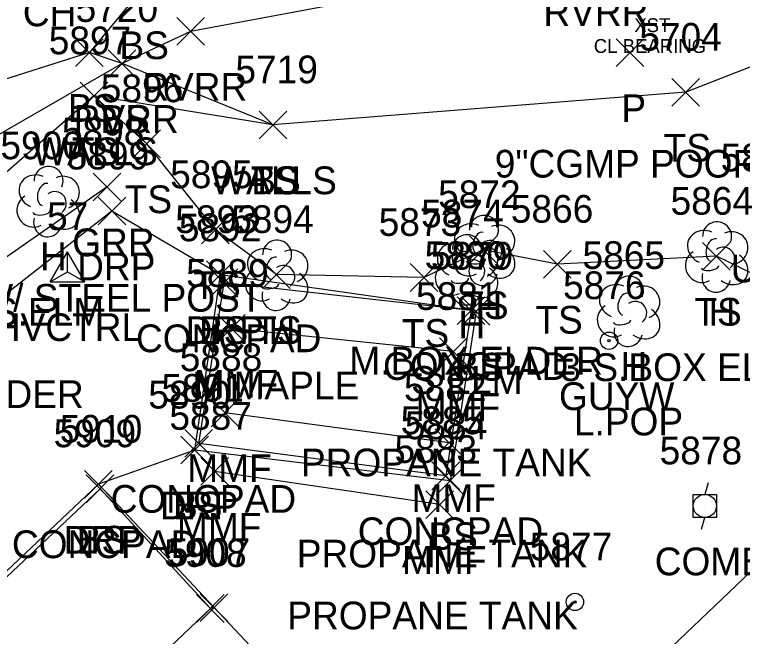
# Model space of a CAD drawing. Extents: x 1618146 to 1620418, y 640749 to 641927.
# Drawn here: x 1620030 to 1620082.5, y 641180.8 to 641225.6 of the extents above; entities that cross this region are included whole.
import ezdxf

# ---------------------------------------------------------------- set-up
doc = ezdxf.new("R2010")
doc.units = 0
for name, color, linetype in [('B_A', 7, 'Continuous'), ('B_C', 7, 'Continuous'), ('C_A', 7, 'Continuous'), ('C_I', 7, 'Continuous'), ('CPSM', 7, 'Continuous'), ('D_A', 7, 'Continuous'), ('D_C', 7, 'Continuous'), ('D_I', 7, 'Continuous'), ('D_TIC', 7, 'Continuous'), ('L_A', 7, 'Continuous'), ('L_C', 7, 'Continuous'), ('L_I', 7, 'Continuous'), ('L_TIC', 7, 'Continuous'), ('LAWE', 7, 'Continuous'), ('LBC', 7, 'Continuous'), ('LDEFAULT', 7, 'Continuous'), ('LELB', 7, 'Continuous'), ('LS', 7, 'Continuous'), ('LTD', 7, 'Continuous'), ('LWS', 7, 'Continuous'), ('R_A', 7, 'Continuous'), ('R_C', 7, 'Continuous'), ('R_I', 7, 'Continuous'), ('R_TIC', 7, 'Continuous'), ('RDP', 7, 'Continuous'), ('RGR', 7, 'Continuous'), ('U_A', 7, 'Continuous'), ('U_I', 7, 'Continuous'), ('UP', 7, 'Continuous'), ('UPGW', 7, 'Continuous')]:
    doc.layers.add(name, color=color, linetype=linetype)

msp = doc.modelspace()

# ---------------------------------------------------------------- linework, layer by layer
at = {"layer": 'CPSM'}
for p, q in [((1620032.603, 641206.338), (1620033.853, 641208.503)), ((1620035.103, 641206.338), (1620033.853, 641208.503)), ((1620033.853, 641207.059), (1620033.853, 641208.503)), ((1620032.603, 641206.338), (1620033.853, 641207.059)), ((1620033.853, 641207.059), (1620033.853, 641207.059)), ((1620033.853, 641207.059), (1620035.103, 641206.338)), ((1620032.603, 641206.338), (1620035.103, 641206.338))]:
    msp.add_line(p, q, dxfattribs=at)
at = {"layer": 'D_TIC'}
for points in [[(1620073.429, 641221.847), (1620075.429, 641223.847)], [(1620075.429, 641221.847), (1620073.429, 641223.847)]]:
    msp.add_lwpolyline(points, dxfattribs=at)
at = {"layer": 'L_TIC'}
for points in [[(1620041.737, 641223.388), (1620043.737, 641225.388)], [(1620043.737, 641223.388), (1620041.737, 641225.388)], [(1620034.445, 641221.864), (1620036.445, 641223.864)], [(1620036.445, 641221.864), (1620034.445, 641223.864)], [(1620034.445, 641221.864), (1620036.445, 641223.864)], [(1620036.445, 641221.864), (1620034.445, 641223.864)], [(1620036.792, 641221.07), (1620038.792, 641223.07)], [(1620038.792, 641221.07), (1620036.792, 641223.07)], [(1620036.792, 641221.07), (1620038.792, 641223.07)], [(1620038.792, 641221.07), (1620036.792, 641223.07)], [(1620077.444, 641218.996), (1620079.444, 641220.996)], [(1620079.444, 641218.996), (1620077.444, 641220.996)], [(1620034.768, 641218.739), (1620036.768, 641220.739)], [(1620036.768, 641218.739), (1620034.768, 641220.739)], [(1620034.768, 641218.739), (1620036.768, 641220.739)], [(1620036.768, 641218.739), (1620034.768, 641220.739)], [(1620047.672, 641216.648), (1620049.672, 641218.648)], [(1620049.672, 641216.648), (1620047.672, 641218.648)], [(1620047.672, 641216.648), (1620049.672, 641218.648)], [(1620049.672, 641216.648), (1620047.672, 641218.648)], [(1620047.672, 641216.648), (1620049.672, 641218.648)], [(1620049.672, 641216.648), (1620047.672, 641218.648)], [(1620038.577, 641215.282), (1620040.577, 641217.282)], [(1620040.577, 641215.282), (1620038.577, 641217.282)], [(1620043.526, 641209.081), (1620045.526, 641211.081)], [(1620045.526, 641209.081), (1620043.526, 641211.081)], [(1620062.849, 641207.645), (1620064.849, 641209.645)], [(1620064.849, 641207.645), (1620062.849, 641209.645)], [(1620079.66, 641207.17), (1620081.66, 641209.17)], [(1620081.66, 641207.17), (1620079.66, 641209.17)], [(1620068.194, 641206.593), (1620070.194, 641208.593)], [(1620070.194, 641206.593), (1620068.194, 641208.593)], [(1620043.893, 641205.844), (1620045.893, 641207.844)], [(1620045.893, 641205.844), (1620043.893, 641207.844)], [(1620047.927, 641205.852), (1620049.927, 641207.852)], [(1620049.927, 641205.852), (1620047.927, 641207.852)], [(1620058.562, 641205.641), (1620060.562, 641207.641)], [(1620060.562, 641205.641), (1620058.562, 641207.641)], [(1620044.153, 641205.256), (1620046.153, 641207.256)], [(1620046.153, 641205.256), (1620044.153, 641207.256)], [(1620044.153, 641205.256), (1620046.153, 641207.256)], [(1620046.153, 641205.256), (1620044.153, 641207.256)], [(1620061.966, 641203.25), (1620063.966, 641205.25)], [(1620063.966, 641203.25), (1620061.966, 641205.25)], [(1620061.966, 641203.25), (1620063.966, 641205.25)], [(1620063.966, 641203.25), (1620061.966, 641205.25)], [(1620062.326, 641203.208), (1620064.326, 641205.208)], [(1620064.326, 641203.208), (1620062.326, 641205.208)], [(1620062.326, 641203.208), (1620064.326, 641205.208)], [(1620064.326, 641203.208), (1620062.326, 641205.208)], [(1620044.686, 641201.966), (1620046.686, 641203.966)], [(1620046.686, 641201.966), (1620044.686, 641203.966)], [(1620060.688, 641200.302), (1620062.688, 641202.302)], [(1620062.688, 641200.302), (1620060.688, 641202.302)], [(1620044.216, 641195.884), (1620046.216, 641197.884)], [(1620046.216, 641195.884), (1620044.216, 641197.884)], [(1620060.386, 641193.729), (1620062.386, 641195.729)], [(1620062.386, 641193.729), (1620060.386, 641195.729)], [(1620042.33, 641193.675), (1620044.33, 641195.675)], [(1620044.33, 641193.675), (1620042.33, 641195.675)], [(1620042.034, 641193.193), (1620044.034, 641195.193)], [(1620044.034, 641193.193), (1620042.034, 641195.193)], [(1620043.469, 641191.658), (1620045.469, 641193.658)], [(1620045.469, 641191.658), (1620043.469, 641193.658)], [(1620060.148, 641191.34), (1620062.148, 641193.34)], [(1620062.148, 641191.34), (1620060.148, 641193.34)], [(1620035.085, 641190.731), (1620037.085, 641192.731)], [(1620037.085, 641190.731), (1620035.085, 641192.731)], [(1620060.45, 641190.979), (1620062.45, 641192.979)], [(1620062.45, 641190.979), (1620060.45, 641192.979)], [(1620035.207, 641190.402), (1620037.207, 641192.402)], [(1620037.207, 641190.402), (1620035.207, 641192.402)], [(1620059.703, 641189.268), (1620061.703, 641191.268)], [(1620061.703, 641189.268), (1620059.703, 641191.268)], [(1620043.169, 641181.771), (1620045.169, 641183.771)], [(1620045.169, 641181.771), (1620043.169, 641183.771)], [(1620043.169, 641181.771), (1620045.169, 641183.771)], [(1620045.169, 641181.771), (1620043.169, 641183.771)], [(1620043.431, 641181.84), (1620045.431, 641183.84)], [(1620045.431, 641181.84), (1620043.431, 641183.84)], [(1620043.431, 641181.84), (1620045.431, 641183.84)], [(1620045.431, 641181.84), (1620043.431, 641183.84)]]:
    msp.add_lwpolyline(points, dxfattribs=at)
at = {"layer": 'LAWE'}
msp.add_lwpolyline([(1620126.924, 641247.392), (1620111.117, 641239.46), (1620109.41, 641236.163), (1620101.636, 641234.759), (1620084.088, 641235.913), (1620071.67, 641229.784), (1620042.737, 641224.388), (1620037.792, 641222.07), (1620025.57, 641215.03), (1620021.304, 641209.771), (1620016.061, 641211.085), (1620004.818, 641210.958), (1619989.454, 641201.04), (1619976.614, 641195.505), (1619948.377, 641191.059)], dxfattribs=at)
at = {"layer": 'LBC'}
msp.add_lwpolyline([(1620182.251, 641113.365), (1620138.873, 641158.876), (1620119.634, 641179.081), (1620099.137, 641200.676), (1620061.444, 641164.754), (1620044.431, 641182.84), (1620044.169, 641182.771), (1620022.603, 641162.294), (1620014.935, 641155.186), (1620024.72, 641144.878), (1620017.727, 641138.107), (1620002.991, 641123.903), (1620002.581, 641122.317), (1620005.727, 641115.216)], dxfattribs=at)
at = {"layer": 'LDEFAULT'}
for points in [[(1620061.688, 641201.302), (1620045.686, 641202.966)], [(1620061.386, 641194.729), (1620045.216, 641196.884)], [(1620060.703, 641190.268), (1620044.469, 641192.658)]]:
    msp.add_lwpolyline(points, dxfattribs=at)
at = {"layer": 'LELB'}
for points in [[(1620126.924, 641247.392), (1620111.61, 641247.659), (1620106.398, 641242.54), (1620098.527, 641237.323), (1620084.828, 641239.216), (1620069.098, 641232.991), (1620064.278, 641237.198), (1620039.166, 641227.389), (1620035.445, 641222.864), (1620023.476, 641219.069), (1620012.158, 641216.975), (1620003.405, 641213.467), (1619988.117, 641206.058), (1619975.419, 641196.769), (1619947.495, 641194.474)], [(1620099.001, 641224.996), (1620087.679, 641223.616), (1620078.444, 641219.996), (1620048.672, 641217.648)], [(1620048.672, 641217.648), (1620037.792, 641222.07), (1620035.445, 641222.864)], [(1620099.137, 641200.676), (1620098.21, 641201.129), (1620087.64, 641204.791), (1620080.66, 641208.17), (1620069.194, 641207.593), (1620063.849, 641208.645), (1620059.562, 641206.641), (1620048.927, 641206.852), (1620044.526, 641210.081), (1620039.577, 641216.282), (1620035.768, 641219.739)], [(1620063.326, 641204.208), (1620044.893, 641206.844)], [(1620063.326, 641204.208), (1620061.45, 641191.979), (1620043.034, 641194.193)], [(1620044.431, 641182.84), (1620036.085, 641191.731)]]:
    msp.add_lwpolyline(points, dxfattribs=at)
at = {"layer": 'LS'}
for points in [[(1620062.966, 641204.25), (1620061.148, 641192.34), (1620043.33, 641194.675), (1620045.153, 641206.256)], [(1620062.966, 641204.25), (1620045.153, 641206.256)], [(1620044.169, 641182.771), (1620036.207, 641191.402), (1620015.554, 641171.939), (1620014.678, 641171.33), (1620022.603, 641162.294)]]:
    msp.add_lwpolyline(points, dxfattribs=at)
at = {"layer": 'LTD'}
for p, q in [((1620032.45, 641212.17), (1620032.45, 641212.17)), ((1620032.45, 641212.17), (1620032.45, 641212.17)), ((1620063.849, 641208.645), (1620063.849, 641208.645)), ((1620063.849, 641208.645), (1620063.849, 641208.645)), ((1620080.66, 641208.17), (1620080.66, 641208.17)), ((1620080.66, 641208.17), (1620080.66, 641208.17)), ((1620048.927, 641206.852), (1620048.927, 641206.852)), ((1620048.927, 641206.852), (1620048.927, 641206.852)), ((1620062.622, 641207.25), (1620062.622, 641207.25)), ((1620062.622, 641207.25), (1620062.622, 641207.25)), ((1620074.309, 641204.257), (1620074.309, 641204.257)), ((1620074.309, 641204.257), (1620074.309, 641204.257))]:
    msp.add_line(p, q, dxfattribs=at)
for centre in [(1620032.497, 641213.604), (1620063.896, 641210.078), (1620080.707, 641209.604), (1620062.669, 641208.684), (1620048.974, 641208.286), (1620074.355, 641205.691)]:
    msp.add_arc(centre, 1.047, 335.5272, 180.9563, dxfattribs=at)
for centre, major_axis, ratio, start_param, end_param in [((1620031.658, 641212.837), (1.21, -0.512), 0.895232, 1.570796, 4.712389), ((1620033.491, 641212.754), (-1.141, -0.483), 0.949671, 1.570796, 4.712389), ((1620032.241, 641212.628), (-0.208, -0.792), 0.645439, 3.141593, 6.283185), ((1620032.95, 641212.003), (-0.5, 0.667), 0.989748, 3.141593, 6.283185), ((1620031.367, 641211.461), (0.584, -1.042), 0.959034, 3.141593, 6.283185), ((1620033.45, 641211.337), (-1.09, 0.792), 0.841452, 1.570796, 4.712389), ((1620031.992, 641211.42), (-0.625, -0.083), 0.423636, 0, 3.141593), ((1620032.45, 641210.67), (0.265, 1.061), 0.942809, 1.570796, 4.712389), ((1620063.058, 641209.311), (1.21, -0.512), 0.895232, 1.570796, 4.712389), ((1620064.891, 641209.228), (-1.141, -0.483), 0.949671, 1.570796, 4.712389), ((1620063.641, 641209.103), (-0.208, -0.792), 0.645439, 3.141593, 6.283185), ((1620079.868, 641208.837), (1.21, -0.512), 0.895232, 1.570796, 4.712389), ((1620081.702, 641208.754), (-1.141, -0.483), 0.949671, 1.570796, 4.712389), ((1620064.349, 641208.478), (-0.5, 0.667), 0.989748, 3.141593, 6.283185), ((1620080.452, 641208.628), (-0.208, -0.792), 0.645439, 3.141593, 6.283185), ((1620048.135, 641207.518), (1.21, -0.512), 0.895232, 1.570796, 4.712389), ((1620061.831, 641207.916), (1.21, -0.512), 0.895232, 1.570796, 4.712389), ((1620062.766, 641207.936), (0.584, -1.042), 0.959034, 3.141593, 6.283185), ((1620063.664, 641207.833), (-1.141, -0.483), 0.949671, 1.570796, 4.712389), ((1620081.16, 641208.003), (-0.5, 0.667), 0.989748, 3.141593, 6.283185), ((1620049.969, 641207.435), (-1.141, -0.483), 0.949671, 1.570796, 4.712389), ((1620062.414, 641207.708), (-0.208, -0.792), 0.645439, 3.141593, 6.283185), ((1620064.85, 641207.811), (-1.09, 0.792), 0.841452, 1.570796, 4.712389), ((1620079.577, 641207.462), (0.584, -1.042), 0.959034, 3.141593, 6.283185), ((1620048.719, 641207.31), (-0.208, -0.792), 0.645439, 3.141593, 6.283185), ((1620063.122, 641207.083), (-0.5, 0.667), 0.989748, 3.141593, 6.283185), ((1620063.391, 641207.894), (-0.625, -0.083), 0.423636, 0, 3.141593), ((1620081.66, 641207.337), (-1.09, 0.792), 0.841452, 1.570796, 4.712389), ((1620049.427, 641206.685), (-0.5, 0.667), 0.989748, 3.141593, 6.283185), ((1620061.539, 641206.541), (0.584, -1.042), 0.959034, 3.141593, 6.283185), ((1620063.85, 641207.145), (0.265, 1.061), 0.942809, 1.570796, 4.712389), ((1620063.622, 641206.417), (-1.09, 0.792), 0.841452, 1.570796, 4.712389), ((1620080.202, 641207.42), (-0.625, -0.083), 0.423636, 0, 3.141593), ((1620047.844, 641206.143), (0.584, -1.042), 0.959034, 3.141593, 6.283185), ((1620049.927, 641206.018), (-1.09, 0.792), 0.841452, 1.570796, 4.712389), ((1620080.66, 641206.67), (0.265, 1.061), 0.942809, 1.570796, 4.712389), ((1620062.164, 641206.5), (-0.625, -0.083), 0.423636, 0, 3.141593), ((1620073.517, 641204.924), (1.21, -0.512), 0.895232, 1.570796, 4.712389), ((1620048.469, 641206.102), (-0.625, -0.083), 0.423636, 0, 3.141593), ((1620062.623, 641205.75), (0.265, 1.061), 0.942809, 1.570796, 4.712389), ((1620075.35, 641204.841), (-1.141, -0.483), 0.949671, 1.570796, 4.712389), ((1620048.927, 641205.352), (0.265, 1.061), 0.942809, 1.570796, 4.712389), ((1620074.1, 641204.716), (-0.208, -0.792), 0.645439, 3.141593, 6.283185), ((1620074.809, 641204.091), (-0.5, 0.667), 0.989748, 3.141593, 6.283185), ((1620073.226, 641203.549), (0.584, -1.042), 0.959034, 3.141593, 6.283185), ((1620075.309, 641203.424), (-1.09, 0.792), 0.841452, 1.570796, 4.712389), ((1620073.851, 641203.507), (-0.625, -0.083), 0.423636, 0, 3.141593), ((1620074.309, 641202.757), (0.265, 1.061), 0.942809, 1.570796, 4.712389)]:
    msp.add_ellipse(centre, major_axis=major_axis, ratio=ratio, start_param=start_param, end_param=end_param, dxfattribs=at)
at = {"layer": 'LWS'}
msp.add_lwpolyline([(1620048.672, 641217.648), (1620035.768, 641219.739), (1620011.761, 641198.789)], dxfattribs=at)
at = {"layer": 'R_TIC'}
for points in [[(1620035.714, 641212.174), (1620037.714, 641214.174)], [(1620037.714, 641212.174), (1620035.714, 641214.174)], [(1620036.069, 641210.433), (1620038.069, 641212.433)], [(1620038.069, 641210.433), (1620036.069, 641212.433)], [(1620043.893, 641205.844), (1620045.893, 641207.844)], [(1620045.893, 641205.844), (1620043.893, 641207.844)], [(1620042.034, 641193.193), (1620044.034, 641195.193)], [(1620044.034, 641193.193), (1620042.034, 641195.193)], [(1620042.034, 641193.193), (1620044.034, 641195.193)], [(1620044.034, 641193.193), (1620042.034, 641195.193)], [(1620035.085, 641190.731), (1620037.085, 641192.731)], [(1620037.085, 641190.731), (1620035.085, 641192.731)]]:
    msp.add_lwpolyline(points, dxfattribs=at)
at = {"layer": 'RDP'}
for points in [[(1620043.034, 641194.193), (1620044.893, 641206.844), (1620037.069, 641211.433), (1620013.614, 641193.094), (1619994.356, 641179.667), (1619979.096, 641167.968), (1619969.083, 641160.779), (1619967.434, 641155.411), (1619967.402, 641148.339), (1619978.796, 641124.54), (1619983.899, 641114.171)], [(1620043.034, 641194.193), (1620036.085, 641191.731), (1620015.329, 641172.126), (1620014.678, 641171.33)]]:
    msp.add_lwpolyline(points, dxfattribs=at)
at = {"layer": 'RGR'}
msp.add_lwpolyline([(1620036.714, 641213.174), (1620026.734, 641206.228), (1620011.856, 641194.678), (1619993.659, 641180.685), (1619978.562, 641168.865), (1619968.756, 641161.751), (1619965.702, 641155.687), (1619966.634, 641148.002), (1619978.242, 641124.494), (1619983.31, 641114)], dxfattribs=at)
at = {"layer": 'UP'}
for p, q in [((1620080.075, 641191.833), (1620079.825, 641191)), ((1620078.992, 641189.333), (1620078.992, 641191)), ((1620078.992, 641191), (1620080.659, 641191)), ((1620080.659, 641191), (1620080.659, 641189.333)), ((1620079.825, 641190.166), (1620079.825, 641190.166)), ((1620080.659, 641189.333), (1620078.992, 641189.333)), ((1620079.575, 641188.5), (1620079.825, 641189.333))]:
    msp.add_line(p, q, dxfattribs=at)
msp.add_circle((1620079.825, 641190.166), 0.833, dxfattribs=at)
at = {"layer": 'UPGW'}
for centre, radius in [((1620072.915, 641202.083), 0.625), ((1620072.915, 641202.083), 0.0833), ((1620070.46, 641183.243), 0.625), ((1620070.46, 641183.243), 0.0833)]:
    msp.add_circle(centre, radius, dxfattribs=at)

# ---------------------------------------------------------------- texts
at = {"layer": 'B_A'}
msp.add_text('XST', height=1, dxfattribs=at).set_placement((1620074.738, 641224.336))
at = {"layer": 'B_C'}
msp.add_text('CL BEARING', height=1, dxfattribs=at).set_placement((1620071.817, 641222.836))
at = {"layer": 'C_A'}
msp.add_text('HVCTRL', height=2, dxfattribs=at).set_placement((1620028.546, 641202.059))
at = {"layer": 'C_I'}
msp.add_text('57', height=2, dxfattribs=at).set_placement((1620032.389, 641210.059))
at = {"layer": 'D_A'}
for s, p in [('P', (1620073.807, 641217.847)), ('UND', (1620081.696, 641206.289))]:
    msp.add_text(s, height=2, dxfattribs=at).set_placement(p)
at = {"layer": 'D_C'}
msp.add_text('9"CGMP POOR', height=2, dxfattribs=at).set_placement((1620064.674, 641213.847))
at = {"layer": 'D_I'}
msp.add_text('5875', height=2, dxfattribs=at).set_placement((1620080.964, 641214.289))
at = {"layer": 'L_A'}
for s, p in [('CH', (1620030.64, 641224.76)), ('RVRR', (1620068.182, 641224.784)), ('BS', (1620037.607, 641222.389)), ('RVRR', (1620039.249, 641219.388)), ('BS', (1620033.886, 641217.864)), ('BS', (1620033.886, 641217.864)), ('RVRR', (1620034.304, 641217.07)), ('BS', (1620036.233, 641217.07)), ('WALLS', (1620031.311, 641214.739)), ('TS', (1620034.177, 641214.739)), ('TS', (1620076.853, 641214.996)), ('WALLS', (1620044.215, 641212.648)), ('TS', (1620047.082, 641212.648)), ('BS', (1620047.113, 641212.648)), ('TS', (1620037.986, 641211.282)), ('H', (1620031.883, 641207.17)), ('TS', (1620042.935, 641205.081)), ('TS', (1620062.259, 641203.645)), ('H', (1620063.282, 641203.645)), ('TS', (1620079.07, 641203.17)), ('H', (1620080.093, 641203.17)), ('H', (1620062.055, 641202.25)), ('TS', (1620067.604, 641202.593)), ('BS', (1620043.334, 641201.844)), ('TS', (1620047.337, 641201.852)), ('H', (1620048.36, 641201.852)), ('TS', (1620057.972, 641201.641)), ('CONCPAD', (1620038.798, 641201.256)), ('CONCPAD', (1620038.798, 641201.256)), ('CONCPAD', (1620056.611, 641199.25)), ('CONCPAD', (1620056.611, 641199.25)), ('BS', (1620061.767, 641199.208)), ('BS', (1620061.767, 641199.208)), ('H', (1620073.742, 641199.257)), ('MMF', (1620042.97, 641197.966)), ('MMF', (1620058.972, 641196.302)), ('MMF', (1620042.5, 641191.884)), ('CONCPAD', (1620036.976, 641189.675)), ('MMF', (1620058.67, 641189.729)), ('BS', (1620041.475, 641189.193)), ('MMF', (1620041.753, 641187.658)), ('CONCPAD', (1620054.794, 641187.34)), ('BS', (1620059.891, 641186.979)), ('CONCPAD', (1620029.852, 641186.402)), ('BS', (1620034.526, 641186.731)), ('MMF', (1620057.987, 641185.268))]:
    msp.add_text(s, height=2, dxfattribs=at).set_placement(p)
at = {"layer": 'L_C'}
for s, p in [('S.ELM', (1620028.481, 641203.17)), ('M.BOX ELDER', (1620054.188, 641199.645)), ('3-S.BOX ELDER', (1620069.408, 641199.17)), ('S.ELM', (1620058.654, 641198.25)), ('M.MAPLE', (1620042.864, 641197.852)), ('S.BOX ELDER', (1620017.198, 641197.228)), ('L.POP', (1620070.38, 641195.257)), ('PROPANE TANK', (1620050.696, 641192.302)), ('PROPANE TANK', (1620050.394, 641185.729)), ('PROPANE TANK', (1620049.711, 641181.268))]:
    msp.add_text(s, height=2, dxfattribs=at).set_placement(p)
at = {"layer": 'L_I'}
for s, p in [('5720', (1620034.446, 641225.07)), ('5720', (1620034.446, 641225.07)), ('5897', (1620032.508, 641222.739)), ('5897', (1620032.508, 641222.739)), ('5704', (1620075.105, 641222.996)), ('5719', (1620045.971, 641220.648)), ('5719', (1620045.971, 641220.648)), ('5719', (1620045.971, 641220.648)), ('5896', (1620036.262, 641219.282)), ('5900', (1620029.025, 641215.17)), ('5895', (1620041.266, 641213.081)), ('5872', (1620060.59, 641211.645)), ('5872', (1620060.59, 641211.645)), ('5864', (1620077.353, 641211.17)), ('5864', (1620077.353, 641211.17)), ('5866', (1620065.832, 641210.593)), ('5874', (1620059.363, 641210.25)), ('5893', (1620041.633, 641209.844)), ('5894', (1620045.667, 641209.852)), ('5894', (1620045.667, 641209.852)), ('5873', (1620056.302, 641209.641)), ('5892', (1620041.893, 641209.256)), ('5892', (1620041.893, 641209.256)), ('5880', (1620059.619, 641207.25)), ('5880', (1620059.619, 641207.25)), ('5879', (1620060.058, 641207.208)), ('5879', (1620060.058, 641207.208)), ('5865', (1620071.002, 641207.257)), ('5889', (1620042.419, 641205.966)), ('5881', (1620058.995, 641204.302)), ('5888', (1620041.956, 641199.884)), ('5891', (1620040.638, 641197.675)), ('5882', (1620058.127, 641197.729)), ('5890', (1620039.687, 641197.193)), ('5887', (1620041.209, 641195.658)), ('5885', (1620057.888, 641195.34)), ('5884', (1620058.191, 641194.979)), ('5909', (1620032.86, 641194.402)), ('5910', (1620033.306, 641194.731)), ('5883', (1620057.444, 641193.268)), ('5907', (1620041.092, 641185.84)), ('5907', (1620041.092, 641185.84)), ('5908', (1620040.831, 641185.771)), ('5908', (1620040.831, 641185.771))]:
    msp.add_text(s, height=2, dxfattribs=at).set_placement(p)
at = {"layer": 'R_A'}
for s, p in [('GRR', (1620034.202, 641208.174)), ('DRP', (1620034.557, 641206.433)), ('DRP', (1620042.381, 641201.844)), ('DRP', (1620040.522, 641189.193)), ('DRP', (1620040.522, 641189.193)), ('DRP', (1620033.573, 641186.731))]:
    msp.add_text(s, height=2, dxfattribs=at).set_placement(p)
at = {"layer": 'R_C'}
msp.add_text('SGR W/ STEEL POST', height=2, dxfattribs=at).set_placement((1620020.879, 641204.174))
at = {"layer": 'R_I'}
for s, p in [('5898', (1620033.454, 641216.174)), ('5899', (1620033.801, 641214.433)), ('5893', (1620041.633, 641209.844)), ('5890', (1620039.687, 641197.193)), ('5890', (1620039.687, 641197.193)), ('5910', (1620033.306, 641194.731))]:
    msp.add_text(s, height=2, dxfattribs=at).set_placement(p)
at = {"layer": 'U_A'}
for s, p in [('GUYW', (1620069.308, 641197.083)), ('COMB', (1620076.211, 641185.166))]:
    msp.add_text(s, height=2, dxfattribs=at).set_placement(p)
at = {"layer": 'U_I'}
for s, p in [('5876', (1620069.6, 641205.083)), ('5878', (1620076.566, 641193.166)), ('5877', (1620067.2, 641186.243))]:
    msp.add_text(s, height=2, dxfattribs=at).set_placement(p)

doc.saveas('drawing.dxf')
